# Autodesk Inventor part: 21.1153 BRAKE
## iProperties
Created: 2007-04
Part Number: 21.1153 BRAKE
Material: ABS Plastic
Document SubType Name: Modeling
Designer: Andy Moles
Mass: 1.71309 g
Surface Area: 17.3522 cm^2
Volume: 1.61612 cm^3
Density: 1.06 g/cm^3
Author: Andy Moles
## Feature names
1. Extrusion1
2. Extrusion2
3. Extrusion3
4. Extrusion4
